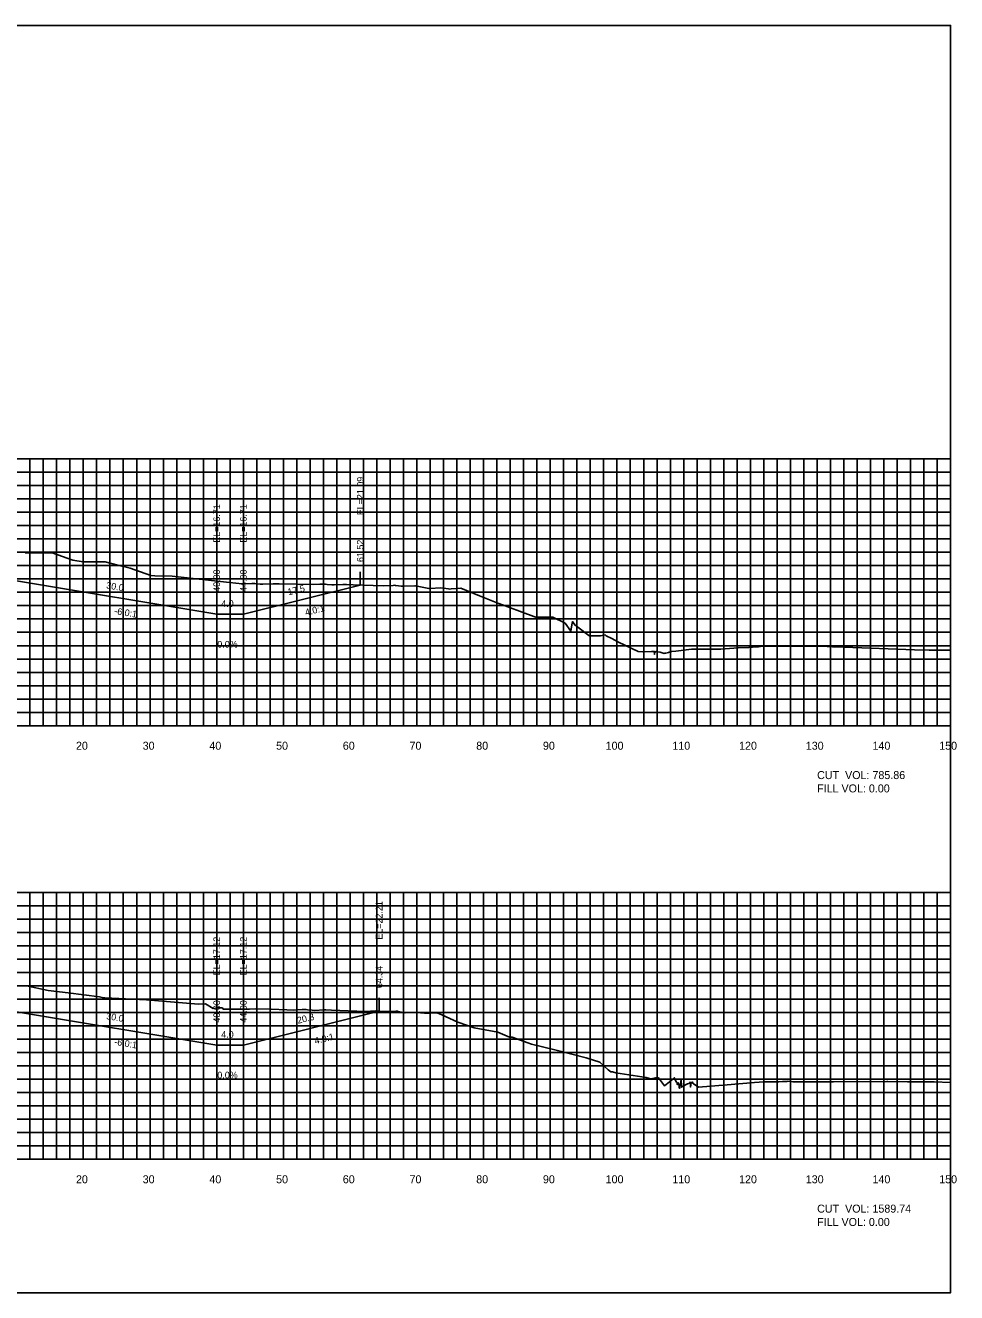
# Model space of a CAD drawing. Extents: x 1800976 to 1805104, y 250057 to 250580.
# Drawn here: x 1802982.3 to 1803121.9, y 250079.4 to 250269.4 of the extents above; entities that cross this region are included whole.
import ezdxf

# ---------------------------------------------------------------- set-up
doc = ezdxf.new("R2010")
doc.units = 0
for name, color, linetype in [('10', 7, 'Continuous'), ('3', 7, 'Continuous'), ('4', 7, 'Continuous'), ('60', 7, 'Continuous'), ('ANNO-TXT', 7, 'Continuous'), ('CL-CNST', 7, 'Continuous'), ('Level 62', 7, 'Continuous'), ('M-ROADS', 7, 'Continuous')]:
    doc.layers.add(name, color=color, linetype=linetype)

msp = doc.modelspace()

# ---------------------------------------------------------------- linework, layer by layer
for p, q in [((1803032.52, 250185.52), (1803032.52, 250187.52)), ((1803011, 250181.14), (1803011, 250183.14)), ((1803015, 250181.14), (1803015, 250183.14)), ((1803035.35, 250121.64), (1803035.35, 250123.64)), ((1803011, 250116.55), (1803011, 250118.55)), ((1803015, 250116.55), (1803015, 250118.55))]:
    msp.add_line(p, q)
msp.add_lwpolyline([(1802821, 250079.43), (1803121, 250079.43), (1803121, 250269.43), (1802821, 250269.43)], close=True)
at = {"layer": '60'}
for p, q in [((1803121, 250164.43), (1803121, 250204.43)), ((1803121.06, 250204.43), (1803121, 250204.43)), ((1803121.06, 250194.43), (1803121, 250194.43)), ((1803121.06, 250184.43), (1803121, 250184.43)), ((1803121.06, 250174.43), (1803121, 250174.43)), ((1802821, 250164.43), (1803121, 250164.43)), ((1802991, 250164.37), (1802991, 250164.43)), ((1803001, 250164.37), (1803001, 250164.43)), ((1803011, 250164.37), (1803011, 250164.43)), ((1803021, 250164.37), (1803021, 250164.43)), ((1803031, 250164.37), (1803031, 250164.43)), ((1803041, 250164.37), (1803041, 250164.43)), ((1803051, 250164.37), (1803051, 250164.43)), ((1803061, 250164.37), (1803061, 250164.43)), ((1803071, 250164.37), (1803071, 250164.43)), ((1803081, 250164.37), (1803081, 250164.43)), ((1803091, 250164.37), (1803091, 250164.43)), ((1803101, 250164.37), (1803101, 250164.43)), ((1803111, 250164.37), (1803111, 250164.43)), ((1803121, 250164.37), (1803121, 250164.43)), ((1803121.06, 250164.43), (1803121, 250164.43)), ((1803121, 250099.43), (1803121, 250139.43)), ((1803121.06, 250139.43), (1803121, 250139.43)), ((1803121.06, 250129.43), (1803121, 250129.43)), ((1803121.06, 250119.43), (1803121, 250119.43)), ((1803121.06, 250109.43), (1803121, 250109.43)), ((1802821, 250099.43), (1803121, 250099.43)), ((1802991, 250099.37), (1802991, 250099.43)), ((1803001, 250099.37), (1803001, 250099.43)), ((1803011, 250099.37), (1803011, 250099.43)), ((1803021, 250099.37), (1803021, 250099.43)), ((1803031, 250099.37), (1803031, 250099.43)), ((1803041, 250099.37), (1803041, 250099.43)), ((1803051, 250099.37), (1803051, 250099.43)), ((1803061, 250099.37), (1803061, 250099.43)), ((1803071, 250099.37), (1803071, 250099.43)), ((1803081, 250099.37), (1803081, 250099.43)), ((1803091, 250099.37), (1803091, 250099.43)), ((1803101, 250099.37), (1803101, 250099.43)), ((1803111, 250099.37), (1803111, 250099.43)), ((1803121, 250099.37), (1803121, 250099.43)), ((1803121.06, 250099.43), (1803121, 250099.43))]:
    msp.add_line(p, q, dxfattribs=at)
at = {"layer": 'CL-CNST'}
for points in [[(1802934.96, 250185.83), (1802940.96, 250186.83), (1802943, 250186.91), (1802947, 250187.07), (1802971, 250186.54), (1802979, 250186.22), (1802981, 250186.14), (1803011, 250181.14), (1803015, 250181.14), (1803032.52, 250185.52)], [(1802935, 250121.24), (1802941, 250122.24), (1802943, 250122.32), (1802947, 250122.48), (1802971, 250121.95), (1802979, 250121.63), (1802981, 250121.55), (1803011, 250116.55), (1803015, 250116.55), (1803035.35, 250121.64)]]:
    msp.add_lwpolyline(points, dxfattribs=at)
at = {"layer": 'Level 62'}
for p, q in [((1802821, 250204.43), (1803121, 250204.43)), ((1802983, 250164.43), (1802983, 250204.43)), ((1802985, 250164.43), (1802985, 250204.43)), ((1802987, 250164.43), (1802987, 250204.43)), ((1802989, 250164.43), (1802989, 250204.43)), ((1802991, 250164.43), (1802991, 250204.43)), ((1802993, 250164.43), (1802993, 250204.43)), ((1802995, 250164.43), (1802995, 250204.43)), ((1802997, 250164.43), (1802997, 250204.43)), ((1802999, 250164.43), (1802999, 250204.43)), ((1803001, 250164.43), (1803001, 250204.43)), ((1803003, 250164.43), (1803003, 250204.43)), ((1803005, 250164.43), (1803005, 250204.43)), ((1803007, 250164.43), (1803007, 250204.43)), ((1803009, 250164.43), (1803009, 250204.43)), ((1803011, 250164.43), (1803011, 250204.43)), ((1803013, 250164.43), (1803013, 250204.43)), ((1803015, 250164.43), (1803015, 250204.43)), ((1803017, 250164.43), (1803017, 250204.43)), ((1803019, 250164.43), (1803019, 250204.43)), ((1803021, 250164.43), (1803021, 250204.43)), ((1803023, 250164.43), (1803023, 250204.43)), ((1803025, 250164.43), (1803025, 250204.43)), ((1803027, 250164.43), (1803027, 250204.43)), ((1803029, 250164.43), (1803029, 250204.43)), ((1803031, 250164.43), (1803031, 250204.43)), ((1803033, 250164.43), (1803033, 250204.43)), ((1803035, 250164.43), (1803035, 250204.43)), ((1803037, 250164.43), (1803037, 250204.43)), ((1803039, 250164.43), (1803039, 250204.43)), ((1803041, 250164.43), (1803041, 250204.43)), ((1803043, 250164.43), (1803043, 250204.43)), ((1803045, 250164.43), (1803045, 250204.43)), ((1803047, 250164.43), (1803047, 250204.43)), ((1803049, 250164.43), (1803049, 250204.43)), ((1803051, 250164.43), (1803051, 250204.43)), ((1803053, 250164.43), (1803053, 250204.43)), ((1803055, 250164.43), (1803055, 250204.43)), ((1803057, 250164.43), (1803057, 250204.43)), ((1803059, 250164.43), (1803059, 250204.43)), ((1803061, 250164.43), (1803061, 250204.43)), ((1803063, 250164.43), (1803063, 250204.43)), ((1803065, 250164.43), (1803065, 250204.43)), ((1803067, 250164.43), (1803067, 250204.43)), ((1803069, 250164.43), (1803069, 250204.43)), ((1803071, 250164.43), (1803071, 250204.43)), ((1803073, 250164.43), (1803073, 250204.43)), ((1803075, 250164.43), (1803075, 250204.43)), ((1803077, 250164.43), (1803077, 250204.43)), ((1803079, 250164.43), (1803079, 250204.43)), ((1803081, 250164.43), (1803081, 250204.43)), ((1803083, 250164.43), (1803083, 250204.43)), ((1803085, 250164.43), (1803085, 250204.43)), ((1803087, 250164.43), (1803087, 250204.43)), ((1803089, 250164.43), (1803089, 250204.43)), ((1803091, 250164.43), (1803091, 250204.43)), ((1803093, 250164.43), (1803093, 250204.43)), ((1803095, 250164.43), (1803095, 250204.43)), ((1803097, 250164.43), (1803097, 250204.43)), ((1803099, 250164.43), (1803099, 250204.43)), ((1803101, 250164.43), (1803101, 250204.43)), ((1803103, 250164.43), (1803103, 250204.43)), ((1803105, 250164.43), (1803105, 250204.43)), ((1803107, 250164.43), (1803107, 250204.43)), ((1803109, 250164.43), (1803109, 250204.43)), ((1803111, 250164.43), (1803111, 250204.43)), ((1803113, 250164.43), (1803113, 250204.43)), ((1803115, 250164.43), (1803115, 250204.43)), ((1803117, 250164.43), (1803117, 250204.43)), ((1803119, 250164.43), (1803119, 250204.43)), ((1803121, 250164.43), (1803121, 250204.43)), ((1802821, 250202.43), (1803121, 250202.43)), ((1802821, 250200.43), (1803121, 250200.43)), ((1802821, 250198.43), (1803121, 250198.43)), ((1802821, 250196.43), (1803121, 250196.43)), ((1802821, 250194.43), (1803121, 250194.43)), ((1802821, 250192.43), (1803121, 250192.43)), ((1802821, 250190.43), (1803121, 250190.43)), ((1802821, 250188.43), (1803121, 250188.43)), ((1802821, 250186.43), (1803121, 250186.43)), ((1802821, 250184.43), (1803121, 250184.43)), ((1802821, 250182.43), (1803121, 250182.43)), ((1802821, 250180.43), (1803121, 250180.43)), ((1802821, 250178.43), (1803121, 250178.43)), ((1802821, 250176.43), (1803121, 250176.43)), ((1802821, 250174.43), (1803121, 250174.43)), ((1802821, 250172.43), (1803121, 250172.43)), ((1802821, 250170.43), (1803121, 250170.43)), ((1802821, 250168.43), (1803121, 250168.43)), ((1802821, 250166.43), (1803121, 250166.43)), ((1802821, 250164.43), (1803121, 250164.43)), ((1802821, 250139.43), (1803121, 250139.43)), ((1802983, 250099.43), (1802983, 250139.43)), ((1802985, 250099.43), (1802985, 250139.43)), ((1802987, 250099.43), (1802987, 250139.43)), ((1802989, 250099.43), (1802989, 250139.43)), ((1802991, 250099.43), (1802991, 250139.43)), ((1802993, 250099.43), (1802993, 250139.43)), ((1802995, 250099.43), (1802995, 250139.43)), ((1802997, 250099.43), (1802997, 250139.43)), ((1802999, 250099.43), (1802999, 250139.43)), ((1803001, 250099.43), (1803001, 250139.43)), ((1803003, 250099.43), (1803003, 250139.43)), ((1803005, 250099.43), (1803005, 250139.43)), ((1803007, 250099.43), (1803007, 250139.43)), ((1803009, 250099.43), (1803009, 250139.43)), ((1803011, 250099.43), (1803011, 250139.43)), ((1803013, 250099.43), (1803013, 250139.43)), ((1803015, 250099.43), (1803015, 250139.43)), ((1803017, 250099.43), (1803017, 250139.43)), ((1803019, 250099.43), (1803019, 250139.43)), ((1803021, 250099.43), (1803021, 250139.43)), ((1803023, 250099.43), (1803023, 250139.43)), ((1803025, 250099.43), (1803025, 250139.43)), ((1803027, 250099.43), (1803027, 250139.43)), ((1803029, 250099.43), (1803029, 250139.43)), ((1803031, 250099.43), (1803031, 250139.43)), ((1803033, 250099.43), (1803033, 250139.43)), ((1803035, 250099.43), (1803035, 250139.43)), ((1803037, 250099.43), (1803037, 250139.43)), ((1803039, 250099.43), (1803039, 250139.43)), ((1803041, 250099.43), (1803041, 250139.43)), ((1803043, 250099.43), (1803043, 250139.43)), ((1803045, 250099.43), (1803045, 250139.43)), ((1803047, 250099.43), (1803047, 250139.43)), ((1803049, 250099.43), (1803049, 250139.43)), ((1803051, 250099.43), (1803051, 250139.43)), ((1803053, 250099.43), (1803053, 250139.43)), ((1803055, 250099.43), (1803055, 250139.43)), ((1803057, 250099.43), (1803057, 250139.43)), ((1803059, 250099.43), (1803059, 250139.43)), ((1803061, 250099.43), (1803061, 250139.43)), ((1803063, 250099.43), (1803063, 250139.43)), ((1803065, 250099.43), (1803065, 250139.43)), ((1803067, 250099.43), (1803067, 250139.43)), ((1803069, 250099.43), (1803069, 250139.43)), ((1803071, 250099.43), (1803071, 250139.43)), ((1803073, 250099.43), (1803073, 250139.43)), ((1803075, 250099.43), (1803075, 250139.43)), ((1803077, 250099.43), (1803077, 250139.43)), ((1803079, 250099.43), (1803079, 250139.43)), ((1803081, 250099.43), (1803081, 250139.43)), ((1803083, 250099.43), (1803083, 250139.43)), ((1803085, 250099.43), (1803085, 250139.43)), ((1803087, 250099.43), (1803087, 250139.43)), ((1803089, 250099.43), (1803089, 250139.43)), ((1803091, 250099.43), (1803091, 250139.43)), ((1803093, 250099.43), (1803093, 250139.43)), ((1803095, 250099.43), (1803095, 250139.43)), ((1803097, 250099.43), (1803097, 250139.43)), ((1803099, 250099.43), (1803099, 250139.43)), ((1803101, 250099.43), (1803101, 250139.43)), ((1803103, 250099.43), (1803103, 250139.43)), ((1803105, 250099.43), (1803105, 250139.43)), ((1803107, 250099.43), (1803107, 250139.43)), ((1803109, 250099.43), (1803109, 250139.43)), ((1803111, 250099.43), (1803111, 250139.43)), ((1803113, 250099.43), (1803113, 250139.43)), ((1803115, 250099.43), (1803115, 250139.43)), ((1803117, 250099.43), (1803117, 250139.43)), ((1803119, 250099.43), (1803119, 250139.43)), ((1803121, 250099.43), (1803121, 250139.43)), ((1802821, 250137.43), (1803121, 250137.43)), ((1802821, 250135.43), (1803121, 250135.43)), ((1802821, 250133.43), (1803121, 250133.43)), ((1802821, 250131.43), (1803121, 250131.43)), ((1802821, 250129.43), (1803121, 250129.43)), ((1802821, 250127.43), (1803121, 250127.43)), ((1802821, 250125.43), (1803121, 250125.43)), ((1802821, 250123.43), (1803121, 250123.43)), ((1802821, 250121.43), (1803121, 250121.43)), ((1802821, 250119.43), (1803121, 250119.43)), ((1802821, 250117.43), (1803121, 250117.43)), ((1802821, 250115.43), (1803121, 250115.43)), ((1802821, 250113.43), (1803121, 250113.43)), ((1802821, 250111.43), (1803121, 250111.43)), ((1802821, 250109.43), (1803121, 250109.43)), ((1802821, 250107.43), (1803121, 250107.43)), ((1802821, 250105.43), (1803121, 250105.43)), ((1802821, 250103.43), (1803121, 250103.43)), ((1802821, 250101.43), (1803121, 250101.43)), ((1802821, 250099.43), (1803121, 250099.43))]:
    msp.add_line(p, q, dxfattribs=at)
at = {"layer": 'M-ROADS'}
for points in [[(1802982.3, 250190.35), (1802984.78, 250190.35), (1802986.34, 250190.35), (1802989.43, 250189.23), (1802991, 250188.98), (1802993.02, 250188.98), (1802994.29, 250188.98), (1802996.19, 250188.5), (1802998.04, 250188.03), (1803001.13, 250186.95), (1803001.73, 250186.92), (1803004.3, 250186.83), (1803012.89, 250185.91), (1803014.81, 250185.68), (1803016.25, 250185.75), (1803016.52, 250185.77), (1803016.58, 250185.76), (1803016.72, 250185.75), (1803017.52, 250185.66), (1803017.91, 250185.63), (1803019.44, 250185.69), (1803019.62, 250185.7), (1803020.35, 250185.68), (1803025.48, 250185.58), (1803026.46, 250185.66), (1803026.87, 250185.66), (1803027.31, 250185.64), (1803027.57, 250185.62), (1803028.24, 250185.57), (1803028.59, 250185.53), (1803029.91, 250185.6), (1803030.28, 250185.62), (1803030.43, 250185.61), (1803031.43, 250185.57), (1803035.96, 250185.38), (1803037.47, 250185.47), (1803037.68, 250185.48), (1803037.73, 250185.47), (1803037.84, 250185.46), (1803038.65, 250185.37), (1803039.07, 250185.33), (1803040.7, 250185.41), (1803040.77, 250185.41), (1803040.82, 250185.4), (1803042.81, 250184.99), (1803043.05, 250185), (1803044.5, 250185.09), (1803045, 250185.03), (1803045.75, 250184.94), (1803045.93, 250184.92), (1803046.12, 250184.93), (1803047.61, 250185.03), (1803050.38, 250183.92), (1803052.89, 250182.91), (1803058.52, 250180.8), (1803058.84, 250180.68), (1803058.88, 250180.68), (1803059.18, 250180.68), (1803061.37, 250180.68), (1803063.21, 250179.79), (1803064.07, 250178.61), (1803064.21, 250179.56), (1803064.33, 250180.04), (1803064.68, 250179.53), (1803065.13, 250179.22), (1803066.78, 250177.94), (1803066.84, 250177.89), (1803068.53, 250177.92), (1803069.25, 250178.04), (1803069.4, 250177.92), (1803070.24, 250177.49), (1803071.24, 250176.96), (1803074.15, 250175.55), (1803074.81, 250175.52), (1803076.15, 250175.58), (1803076.22, 250175.57), (1803076.53, 250175.56), (1803076.57, 250175.56), (1803076.58, 250175.56), (1803076.62, 250175.21), (1803076.63, 250175.18), (1803076.63, 250175.13), (1803076.63, 250175.41), (1803076.85, 250175.54), (1803076.94, 250175.54), (1803077.11, 250175.53), (1803077.46, 250175.48), (1803078.08, 250175.28), (1803078.18, 250175.31), (1803078.32, 250175.31), (1803078.74, 250175.42), (1803079.05, 250175.56), (1803079.07, 250175.56), (1803079.12, 250175.57), (1803079.2, 250175.57), (1803079.84, 250175.61), (1803082.17, 250175.92), (1803084.17, 250175.92), (1803085.43, 250175.92), (1803086.59, 250175.93), (1803089.15, 250176.11), (1803090.75, 250176.18), (1803091.84, 250176.25), (1803091.94, 250176.26), (1803092.04, 250176.26), (1803092.17, 250176.28), (1803092.19, 250176.27), (1803092.52, 250176.29), (1803096.24, 250176.35), (1803096.25, 250176.35), (1803096.31, 250176.35), (1803096.41, 250176.35), (1803098.83, 250176.35), (1803100.36, 250176.35), (1803101.64, 250176.34), (1803103.3, 250176.26), (1803105.04, 250176.2), (1803115.6, 250175.82), (1803117.81, 250175.76), (1803119.37, 250175.77), (1803120.95, 250175.78), (1803121, 250175.78)], [(1802980.64, 250125.41), (1802982.5, 250125.44), (1802985.74, 250124.74), (1802988.73, 250124.36), (1802993.43, 250123.76), (1802993.81, 250123.69), (1802993.85, 250123.68), (1802994.24, 250123.65), (1803000.46, 250123.33), (1803008.28, 250122.66), (1803009.3, 250122.72), (1803010.45, 250122.05), (1803011.18, 250122.15), (1803011.85, 250122.12), (1803011.96, 250121.94), (1803013.11, 250121.91), (1803013.5, 250121.95), (1803014.36, 250121.95), (1803014.37, 250121.95), (1803014.37, 250121.95), (1803015.56, 250121.91), (1803015.92, 250121.93), (1803016.77, 250121.97), (1803019.17, 250121.91), (1803021.49, 250121.84), (1803022.56, 250121.8), (1803023.1, 250121.81), (1803023.81, 250121.86), (1803024.09, 250121.88), (1803024.27, 250121.88), (1803024.39, 250121.86), (1803024.61, 250121.85), (1803025.3, 250121.79), (1803025.66, 250121.75), (1803027.09, 250121.82), (1803027.38, 250121.83), (1803028.21, 250121.8), (1803033.27, 250121.6), (1803034.86, 250121.66), (1803035, 250121.66), (1803035.12, 250121.66), (1803035.86, 250121.6), (1803036.37, 250121.56), (1803037.83, 250121.62), (1803038.09, 250121.63), (1803038.2, 250121.6), (1803039.23, 250121.37), (1803040.3, 250121.41), (1803040.92, 250121.43), (1803041.06, 250121.42), (1803041.56, 250121.38), (1803042.17, 250121.33), (1803042.34, 250121.32), (1803043.08, 250121.35), (1803044.03, 250121.39), (1803044.74, 250121.07), (1803047.12, 250119.97), (1803049.59, 250119.13), (1803053.14, 250118.48), (1803054.9, 250117.74), (1803055.31, 250117.73), (1803057.64, 250116.87), (1803058.16, 250116.71), (1803062.08, 250115.72), (1803066.39, 250114.64), (1803068.45, 250113.97), (1803069.66, 250112.83), (1803070.09, 250112.55), (1803070.32, 250112.56), (1803070.84, 250112.39), (1803075.35, 250111.67), (1803076.05, 250111.51), (1803077.02, 250111.67), (1803077.23, 250111.62), (1803078.14, 250110.43), (1803079.37, 250111.46), (1803079.57, 250111.62), (1803079.58, 250111.66), (1803079.93, 250111), (1803079.99, 250110.93), (1803080, 250110.94), (1803080.01, 250110.92), (1803080.03, 250110.71), (1803080.03, 250110.62), (1803080.03, 250110.68), (1803080.04, 250110.63), (1803080.05, 250110.74), (1803080.17, 250110.9), (1803080.31, 250110.48), (1803080.33, 250110.2), (1803080.35, 250110.09), (1803080.41, 250110.09), (1803080.41, 250110.07), (1803080.41, 250110.45), (1803080.42, 250110.46), (1803080.44, 250110.19), (1803080.61, 250111.4), (1803080.61, 250111.4), (1803080.62, 250111.4), (1803080.63, 250111.09), (1803080.72, 250110.23), (1803080.74, 250110.28), (1803080.74, 250110.27), (1803081.58, 250110.73), (1803081.94, 250110.86), (1803081.96, 250111), (1803082.02, 250110.56), (1803082.03, 250110.51), (1803082.04, 250110.26), (1803082.05, 250110.55), (1803082.12, 250110.93), (1803082.31, 250111.01), (1803082.35, 250110.82), (1803082.49, 250110.75), (1803083, 250110.4), (1803083.2, 250110.22), (1803087.53, 250110.6), (1803091.62, 250110.95), (1803092.99, 250111.02), (1803094.85, 250111.02), (1803094.89, 250111.02), (1803095.28, 250111.03), (1803095.79, 250111.1), (1803095.85, 250111.07), (1803096.49, 250111.11), (1803096.54, 250111.13), (1803097.35, 250111.02), (1803097.4, 250111.02), (1803097.47, 250111.02), (1803098.29, 250111.03), (1803103.45, 250111.05), (1803111.44, 250111.08), (1803111.6, 250111.07), (1803114.53, 250111.04), (1803116.82, 250111.04), (1803118.54, 250111.03), (1803121, 250110.95)]]:
    msp.add_lwpolyline(points, dxfattribs=at)

# ---------------------------------------------------------------- texts
for s, rotation, p in [('4.0:1', 14.0362, (1803024.37, 250180.91)), ('-6.0:1', 350.5377, (1802995.59, 250181.18)), ('4.0:1', 14.0362, (1803025.78, 250116.67)), ('-6.0:1', 350.5377, (1802995.59, 250116.59))]:
    msp.add_text(s, height=1, rotation=rotation).set_placement(p)
at = {"layer": '10'}
for s, p in [('20', (1802989.9, 250160.83)), ('30', (1802999.9, 250160.83)), ('40', (1803009.9, 250160.83)), ('50', (1803019.9, 250160.83)), ('60', (1803029.9, 250160.83)), ('70', (1803039.9, 250160.83)), ('80', (1803049.9, 250160.83)), ('90', (1803059.9, 250160.83)), ('100', (1803069.3, 250160.83)), ('110', (1803079.3, 250160.83)), ('120', (1803089.3, 250160.83)), ('130', (1803099.3, 250160.83)), ('140', (1803109.3, 250160.83)), ('150', (1803119.3, 250160.83)), ('20', (1802989.9, 250095.83)), ('30', (1802999.9, 250095.83)), ('40', (1803009.9, 250095.83)), ('50', (1803019.9, 250095.83)), ('60', (1803029.9, 250095.83)), ('70', (1803039.9, 250095.83)), ('80', (1803049.9, 250095.83)), ('90', (1803059.9, 250095.83)), ('100', (1803069.3, 250095.83)), ('110', (1803079.3, 250095.83)), ('120', (1803089.3, 250095.83)), ('130', (1803099.3, 250095.83)), ('140', (1803109.3, 250095.83)), ('150', (1803119.3, 250095.83))]:
    msp.add_text(s, height=1.2, dxfattribs=at).set_placement(p)
at = {"layer": '3'}
for s, p in [('EL=21.09', (1803033.02, 250195.99)), ('EL=16.71', (1803011.5, 250191.87)), ('EL=16.71', (1803015.5, 250191.87)), ('61.52', (1803033.02, 250188.97)), ('40.00', (1803011.5, 250184.51)), ('44.00', (1803015.5, 250184.51)), ('EL=22.21', (1803035.85, 250132.36)), ('EL=17.12', (1803011.5, 250127.02)), ('EL=17.12', (1803015.5, 250127.02)), ('64.34', (1803035.85, 250125.09)), ('40.00', (1803011.5, 250119.92)), ('44.00', (1803015.5, 250119.92))]:
    msp.add_text(s, height=1, rotation=90, dxfattribs=at).set_placement(p)
at = {"layer": '4'}
for s, rotation, p in [('30.0', 350.5377, (1802994.39, 250185.03)), ('17.5', 14.0362, (1803021.77, 250183.97)), ('30.0', 350.5377, (1802994.39, 250120.44)), ('20.3', 14.0362, (1803023.18, 250119.73))]:
    msp.add_text(s, height=1, rotation=rotation, dxfattribs=at).set_placement(p)
for s, p in [('4.0', (1803011.68, 250182.24)), ('0.0%', (1803011.09, 250176.14)), ('4.0', (1803011.68, 250117.65)), ('0.0%', (1803011.09, 250111.55))]:
    msp.add_text(s, height=1, dxfattribs=at).set_placement(p)
at = {"layer": 'ANNO-TXT'}
for s, p in [('CUT  VOL: 785.86', (1803101, 250156.43)), ('FILL VOL: 0.00', (1803101, 250154.43)), ('CUT  VOL: 1589.74', (1803101, 250091.43)), ('FILL VOL: 0.00', (1803101, 250089.43))]:
    msp.add_text(s, height=1.2, dxfattribs=at).set_placement(p)

doc.saveas('drawing.dxf')
